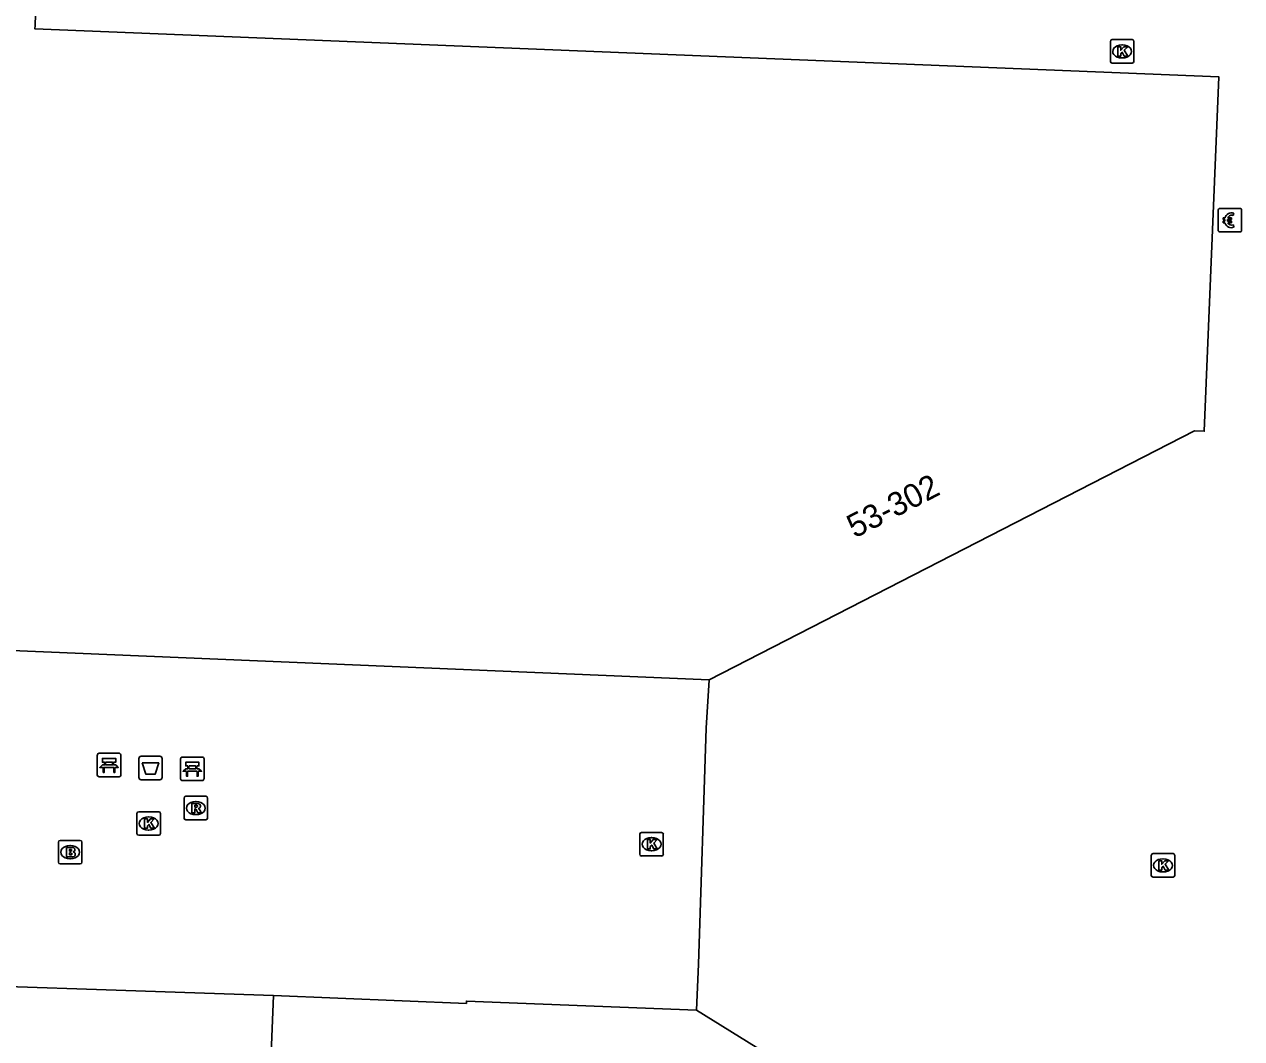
# Model space of a CAD drawing. Extents: x 160891 to 161384, y 386490 to 386907.
# Drawn here: x 161186.2 to 161238, y 386705.9 to 386749.1 of the extents above; entities that cross this region are included whole.
import ezdxf

# ---------------------------------------------------------------- set-up
doc = ezdxf.new("R2010")
doc.units = 0
for name, color, linetype in [('IMGEO_Afvalbak', 7, 'Continuous'), ('IMGEO_Bank', 7, 'Continuous'), ('IMGEO_Betaalautomaat', 7, 'Continuous'), ('IMGEO_Brandkraan', 7, 'Continuous'), ('IMGEO_Hek', 7, 'Continuous'), ('IMGEO_Kolk', 7, 'Continuous'), ('IMGEO_Pand', 7, 'Continuous'), ('IMGEO_Pand_nummerreeks', 7, 'Continuous'), ('IMGEO_Rioolput', 7, 'Continuous'), ('IMGEO_Voetgangersgebied_open', 7, 'Continuous')]:
    doc.layers.add(name, color=color, linetype=linetype)

msp = doc.modelspace()

# ---------------------------------------------------------------- linework, layer by layer
at = {"layer": 'IMGEO_Afvalbak'}
for p, q in [((161191.071, 386717.061), (161191.071, 386717.861)), ((161191.071, 386717.861), (161191.071, 386717.061)), ((161191.171, 386717.961), (161191.961, 386717.961)), ((161191.961, 386717.961), (161191.171, 386717.961)), ((161192.061, 386717.861), (161192.061, 386717.061)), ((161192.061, 386717.061), (161192.061, 386717.861)), ((161191.961, 386716.961), (161191.171, 386716.961)), ((161191.171, 386716.961), (161191.961, 386716.961))]:
    msp.add_line(p, q, dxfattribs=at)
msp.add_lwpolyline([(161191.214, 386717.675), (161191.918, 386717.675), (161191.769, 386717.205), (161191.363, 386717.205), (161191.214, 386717.675)], dxfattribs=at)
for centre, start, end in [((161191.171, 386717.861), 90, 180), ((161191.171, 386717.861), 90, 180), ((161191.961, 386717.861), 0, 90), ((161191.961, 386717.861), 360, 90), ((161191.171, 386717.061), 180, 270), ((161191.171, 386717.061), 180, 270), ((161191.961, 386717.061), 270, 0), ((161191.961, 386717.061), 270, 0)]:
    msp.add_arc(centre, 0.1, start, end, dxfattribs=at)
at = {"layer": 'IMGEO_Bank'}
for p, q in [((161189.304, 386717.165), (161189.304, 386718.006)), ((161189.304, 386718.006), (161189.304, 386717.165)), ((161189.379, 386718.09), (161190.22, 386718.09)), ((161190.22, 386718.09), (161189.379, 386718.09)), ((161189.613, 386717.596), (161189.613, 386717.702)), ((161189.657, 386717.702), (161189.657, 386717.596)), ((161189.945, 386717.708), (161189.663, 386717.708)), ((161189.951, 386717.596), (161189.951, 386717.702)), ((161189.995, 386717.702), (161189.995, 386717.596)), ((161190.304, 386718.015), (161190.304, 386717.174)), ((161190.304, 386717.174), (161190.304, 386718.015)), ((161192.844, 386717.003), (161192.844, 386717.844)), ((161192.844, 386717.844), (161192.844, 386717.003)), ((161192.919, 386717.928), (161193.76, 386717.928)), ((161193.76, 386717.928), (161192.919, 386717.928)), ((161193.844, 386717.853), (161193.844, 386717.012)), ((161193.844, 386717.012), (161193.844, 386717.853)), ((161190.001, 386717.488), (161189.608, 386717.488)), ((161189.663, 386717.59), (161189.945, 386717.59)), ((161193.541, 386717.326), (161193.148, 386717.326)), ((161193.153, 386717.434), (161193.153, 386717.54)), ((161193.197, 386717.54), (161193.197, 386717.434)), ((161193.485, 386717.546), (161193.203, 386717.546)), ((161193.203, 386717.428), (161193.485, 386717.428)), ((161193.491, 386717.434), (161193.491, 386717.54)), ((161193.535, 386717.54), (161193.535, 386717.434)), ((161190.229, 386717.09), (161189.388, 386717.09)), ((161189.388, 386717.09), (161190.229, 386717.09)), ((161193.769, 386716.928), (161192.928, 386716.928)), ((161192.928, 386716.928), (161193.769, 386716.928))]:
    msp.add_line(p, q, dxfattribs=at)
for points in [[(161189.607, 386717.708), (161189.521, 386717.708), (161189.521, 386717.869), (161190.084, 386717.869), (161190.084, 386717.708), (161190.001, 386717.708)], [(161193.147, 386717.546), (161193.061, 386717.546), (161193.061, 386717.707), (161193.624, 386717.707), (161193.624, 386717.546), (161193.541, 386717.546)], [(161189.551, 386717.488), (161189.409, 386717.488), (161189.521, 386717.59), (161189.607, 386717.59)], [(161189.601, 386717.481), (161189.601, 386717.274), (161189.558, 386717.274), (161189.558, 386717.481)], [(161190.001, 386717.59), (161190.084, 386717.59), (161190.196, 386717.488), (161190.057, 386717.488)], [(161190.051, 386717.481), (161190.051, 386717.274), (161190.007, 386717.274), (161190.007, 386717.481)], [(161193.091, 386717.326), (161192.949, 386717.326), (161193.061, 386717.428), (161193.147, 386717.428)], [(161193.141, 386717.319), (161193.141, 386717.112), (161193.098, 386717.112), (161193.098, 386717.319)], [(161193.541, 386717.428), (161193.624, 386717.428), (161193.736, 386717.326), (161193.597, 386717.326)], [(161193.591, 386717.319), (161193.591, 386717.112), (161193.547, 386717.112), (161193.547, 386717.319)]]:
    msp.add_lwpolyline(points, dxfattribs=at)
for centre, radius, start, end in [((161189.382, 386718.012), 0.0779, 92.4484, 184.2845), ((161189.382, 386718.012), 0.0779, 92.4484, 184.2845), ((161189.606, 386717.701), 0.00671, 2.8957, 87.1043), ((161189.663, 386717.701), 0.00671, 92.8957, 177.1043), ((161189.945, 386717.701), 0.00671, 2.8957, 87.1043), ((161190.002, 386717.701), 0.00671, 92.8957, 177.1043), ((161190.226, 386718.012), 0.0779, 2.4484, 94.2845), ((161190.226, 386718.012), 0.0779, 2.4484, 94.2845), ((161192.922, 386717.85), 0.0779, 92.4484, 184.2845), ((161192.922, 386717.85), 0.0779, 92.4484, 184.2845), ((161193.766, 386717.85), 0.0779, 2.4484, 94.2845), ((161193.766, 386717.85), 0.0779, 2.4484, 94.2845), ((161189.382, 386717.168), 0.0779, 182.4484, 274.2845), ((161189.382, 386717.168), 0.0779, 182.4484, 274.2845), ((161189.551, 386717.481), 0.00671, 2.8957, 87.1043), ((161189.608, 386717.481), 0.00671, 92.8957, 177.1043), ((161189.606, 386717.597), 0.00671, 272.8957, 357.1043), ((161189.663, 386717.597), 0.00671, 182.8957, 267.1043), ((161189.945, 386717.597), 0.00671, 272.8957, 357.1043), ((161190.002, 386717.597), 0.00671, 182.8957, 267.1043), ((161190, 386717.481), 0.00671, 2.8957, 87.1043), ((161190.057, 386717.481), 0.00671, 92.8957, 177.1043), ((161190.226, 386717.168), 0.0779, 272.4484, 4.2845), ((161190.226, 386717.168), 0.0779, 272.4484, 4.2845), ((161193.091, 386717.319), 0.00671, 2.8957, 87.1043), ((161193.148, 386717.319), 0.00671, 92.8957, 177.1043), ((161193.146, 386717.539), 0.00671, 2.8957, 87.1043), ((161193.146, 386717.435), 0.00671, 272.8957, 357.1043), ((161193.203, 386717.539), 0.00671, 92.8957, 177.1043), ((161193.203, 386717.435), 0.00671, 182.8957, 267.1043), ((161193.485, 386717.539), 0.00671, 2.8957, 87.1043), ((161193.485, 386717.435), 0.00671, 272.8957, 357.1043), ((161193.542, 386717.539), 0.00671, 92.8957, 177.1043), ((161193.542, 386717.435), 0.00671, 182.8957, 267.1043), ((161193.54, 386717.319), 0.00671, 2.8957, 87.1043), ((161193.597, 386717.319), 0.00671, 92.8957, 177.1043), ((161192.922, 386717.006), 0.0779, 182.4484, 274.2845), ((161192.922, 386717.006), 0.0779, 182.4484, 274.2845), ((161193.766, 386717.006), 0.0779, 272.4484, 4.2845), ((161193.766, 386717.006), 0.0779, 272.4484, 4.2845)]:
    msp.add_arc(centre, radius, start, end, dxfattribs=at)
at = {"layer": 'IMGEO_Betaalautomaat'}
for p, q in [((161236.966, 386740.342), (161236.966, 386741.183)), ((161236.966, 386741.183), (161236.966, 386740.342)), ((161237.041, 386741.266), (161237.882, 386741.266)), ((161237.882, 386741.266), (161237.041, 386741.266)), ((161237.628, 386741.071), (161237.611, 386740.971)), ((161237.965, 386741.192), (161237.965, 386740.351)), ((161237.965, 386740.351), (161237.965, 386741.192)), ((161237.249, 386740.73), (161237.249, 386740.798)), ((161237.37, 386740.798), (161237.37, 386740.73)), ((161237.615, 386740.565), (161237.637, 386740.478)), ((161237.891, 386740.267), (161237.05, 386740.267)), ((161237.05, 386740.267), (161237.891, 386740.267))]:
    msp.add_line(p, q, dxfattribs=at)
for points in [[(161237.249, 386740.798), (161237.18, 386740.798), (161237.18, 386740.867), (161237.259, 386740.867)], [(161237.254, 386740.661), (161237.18, 386740.661), (161237.18, 386740.73), (161237.249, 386740.73)], [(161237.381, 386740.867), (161237.528, 386740.867), (161237.528, 386740.798), (161237.37, 386740.798)], [(161237.37, 386740.73), (161237.528, 386740.73), (161237.528, 386740.661), (161237.384, 386740.661)]]:
    msp.add_lwpolyline(points, dxfattribs=at)
for centre, radius, start, end in [((161237.044, 386741.189), 0.0779, 92.4484, 184.2845), ((161237.044, 386741.189), 0.0779, 92.4484, 184.2845), ((161237.542, 386740.791), 0.293, 73.014, 165.0139), ((161237.548, 386740.804), 0.179, 69.3236, 159.5683), ((161237.888, 386741.189), 0.0779, 2.4484, 94.2845), ((161237.888, 386741.189), 0.0779, 2.4484, 94.2845), ((161237.515, 386740.716), 0.267, 191.8096, 297.0389), ((161237.548, 386740.731), 0.179, 202.7625, 291.8693), ((161237.044, 386740.345), 0.0779, 182.4484, 274.2845), ((161237.044, 386740.345), 0.0779, 182.4484, 274.2845), ((161237.888, 386740.345), 0.0779, 272.4484, 4.2845), ((161237.888, 386740.345), 0.0779, 272.4484, 4.2845)]:
    msp.add_arc(centre, radius, start, end, dxfattribs=at)
at = {"layer": 'IMGEO_Brandkraan'}
for p, q in [((161187.649, 386713.454), (161187.649, 386714.306)), ((161187.724, 386714.38), (161188.576, 386714.38)), ((161188.137, 386714.16), (161188.162, 386714.16)), ((161188.65, 386714.306), (161188.65, 386713.454)), ((161188.16, 386713.6), (161188.135, 386713.6)), ((161188.576, 386713.38), (161187.724, 386713.38))]:
    msp.add_line(p, q, dxfattribs=at)
for points in [[(161187.649, 386713.454), (161187.649, 386714.306)], [(161187.724, 386714.38), (161188.576, 386714.38)], [(161187.997, 386714.08), (161187.997, 386713.68), (161188.21, 386713.68)], [(161188.228, 386714.08), (161187.997, 386714.08)], [(161188.65, 386714.306), (161188.65, 386713.454)], [(161188.176, 386713.999), (161188.122, 386713.999), (161188.122, 386713.923)], [(161188.122, 386713.923), (161188.175, 386713.923)], [(161188.184, 386713.847), (161188.122, 386713.847), (161188.122, 386713.766)], [(161188.122, 386713.766), (161188.184, 386713.766)], [(161188.576, 386713.38), (161187.724, 386713.38)]]:
    msp.add_lwpolyline(points, dxfattribs=at)
for centre, radius, start, end in [((161187.726, 386714.304), 0.0765, 91.552, 178.448), ((161187.726, 386714.304), 0.0765, 91.552, 178.448), ((161188.232, 386713.935), 0.145, 59.4692, 91.5367), ((161188.257, 386713.982), 0.0922, 285.5137, 58.1501), ((161188.574, 386714.304), 0.0765, 1.552, 88.448), ((161188.574, 386714.304), 0.0765, 1.552, 88.448), ((161188.177, 386713.961), 0.0379, 267.8285, 90.9355), ((161188.185, 386713.806), 0.0404, 269.8759, 90.5077), ((161188.216, 386713.931), 0.251, 268.6676, 293.5347), ((161188.262, 386713.79), 0.105, 301.3115, 78.989), ((161187.726, 386713.456), 0.0765, 181.552, 268.448), ((161187.726, 386713.456), 0.0765, 181.552, 268.448), ((161188.574, 386713.456), 0.0765, 271.552, 358.448), ((161188.574, 386713.456), 0.0765, 271.552, 358.448)]:
    msp.add_arc(centre, radius, start, end, dxfattribs=at)
for centre, major_axis, ratio, start_param, end_param in [((161188.136, 386713.88), (-0.387, 0.002), 0.722429, 4.712389, 7.853982), ((161188.161, 386713.88), (-0.39, 0.002), 0.717154, 1.570796, 4.712389)]:
    msp.add_ellipse(centre, major_axis=major_axis, ratio=ratio, start_param=start_param, end_param=end_param, dxfattribs=at)
at = {"layer": 'IMGEO_Hek'}
for points in [[(161215.329, 386721.218), (161215.194, 386719.154)], [(161215.194, 386719.154), (161214.868, 386709.114)], [(161214.868, 386709.114), (161214.777, 386707.152)]]:
    msp.add_lwpolyline(points, dxfattribs=at)
at = {"layer": 'IMGEO_Kolk'}
for p, q in [((161232.382, 386747.523), (161232.382, 386748.375)), ((161232.457, 386748.449), (161233.309, 386748.449)), ((161232.87, 386748.229), (161232.895, 386748.229)), ((161233.383, 386748.375), (161233.383, 386747.523)), ((161233.309, 386747.449), (161232.457, 386747.449)), ((161232.893, 386747.669), (161232.868, 386747.669)), ((161191.062, 386715.599), (161191.914, 386715.599)), ((161190.987, 386714.673), (161190.987, 386715.525)), ((161191.475, 386715.379), (161191.5, 386715.379)), ((161191.988, 386715.525), (161191.988, 386714.673)), ((161191.914, 386714.599), (161191.062, 386714.599)), ((161191.498, 386714.819), (161191.473, 386714.819)), ((161212.372, 386713.791), (161212.372, 386714.643)), ((161212.447, 386714.717), (161213.299, 386714.717)), ((161213.373, 386714.643), (161213.373, 386713.791)), ((161212.86, 386714.497), (161212.885, 386714.497)), ((161213.299, 386713.717), (161212.447, 386713.717)), ((161212.883, 386713.937), (161212.858, 386713.937)), ((161234.121, 386712.892), (161234.121, 386713.744)), ((161234.196, 386713.818), (161235.048, 386713.818)), ((161234.609, 386713.598), (161234.634, 386713.598)), ((161235.122, 386713.744), (161235.122, 386712.892)), ((161234.632, 386713.038), (161234.607, 386713.038)), ((161235.048, 386712.818), (161234.196, 386712.818))]:
    msp.add_line(p, q, dxfattribs=at)
for points in [[(161232.382, 386747.523), (161232.382, 386748.375)], [(161232.457, 386748.449), (161233.309, 386748.449)], [(161233.383, 386748.375), (161233.383, 386747.523)], [(161232.703, 386748.149), (161232.826, 386748.149), (161232.826, 386747.998), (161232.956, 386748.149), (161233.12, 386748.149), (161232.974, 386747.998), (161233.127, 386747.749), (161232.975, 386747.749), (161232.89, 386747.913), (161232.826, 386747.846), (161232.826, 386747.749), (161232.703, 386747.749), (161232.703, 386748.149)], [(161233.309, 386747.449), (161232.457, 386747.449)], [(161191.062, 386715.599), (161191.914, 386715.599)], [(161190.987, 386714.673), (161190.987, 386715.525)], [(161191.308, 386715.299), (161191.431, 386715.299), (161191.431, 386715.148), (161191.561, 386715.299), (161191.725, 386715.299), (161191.579, 386715.148), (161191.732, 386714.899), (161191.58, 386714.899), (161191.495, 386715.063), (161191.431, 386714.996), (161191.431, 386714.899), (161191.308, 386714.899), (161191.308, 386715.299)], [(161191.988, 386715.525), (161191.988, 386714.673)], [(161191.914, 386714.599), (161191.062, 386714.599)], [(161212.372, 386713.791), (161212.372, 386714.643)], [(161212.447, 386714.717), (161213.299, 386714.717)], [(161213.373, 386714.643), (161213.373, 386713.791)], [(161212.693, 386714.417), (161212.816, 386714.417), (161212.816, 386714.266), (161212.946, 386714.417), (161213.11, 386714.417), (161212.964, 386714.266), (161213.117, 386714.017), (161212.965, 386714.017), (161212.88, 386714.181), (161212.816, 386714.114), (161212.816, 386714.017), (161212.693, 386714.017), (161212.693, 386714.417)], [(161213.299, 386713.717), (161212.447, 386713.717)], [(161234.121, 386712.892), (161234.121, 386713.744)], [(161234.196, 386713.818), (161235.048, 386713.818)], [(161234.442, 386713.518), (161234.565, 386713.518), (161234.565, 386713.367), (161234.695, 386713.518), (161234.859, 386713.518), (161234.713, 386713.367), (161234.866, 386713.118), (161234.714, 386713.118), (161234.629, 386713.282), (161234.565, 386713.215), (161234.565, 386713.118), (161234.442, 386713.118), (161234.442, 386713.518)], [(161235.122, 386713.744), (161235.122, 386712.892)], [(161235.048, 386712.818), (161234.196, 386712.818)]]:
    msp.add_lwpolyline(points, dxfattribs=at)
for centre, start, end in [((161232.459, 386748.373), 91.552, 178.448), ((161232.459, 386748.373), 91.552, 178.448), ((161233.307, 386748.373), 1.552, 88.448), ((161233.307, 386748.373), 1.552, 88.448), ((161232.459, 386747.525), 181.552, 268.448), ((161232.459, 386747.525), 181.552, 268.448), ((161233.307, 386747.525), 271.552, 358.448), ((161233.307, 386747.525), 271.552, 358.448), ((161191.064, 386715.523), 91.552, 178.448), ((161191.064, 386715.523), 91.552, 178.448), ((161191.912, 386715.523), 1.552, 88.448), ((161191.912, 386715.523), 1.552, 88.448), ((161191.064, 386714.675), 181.552, 268.448), ((161191.064, 386714.675), 181.552, 268.448), ((161191.912, 386714.675), 271.552, 358.448), ((161191.912, 386714.675), 271.552, 358.448), ((161212.449, 386714.641), 91.552, 178.448), ((161212.449, 386714.641), 91.552, 178.448), ((161213.297, 386714.641), 1.552, 88.448), ((161213.297, 386714.641), 1.552, 88.448), ((161212.449, 386713.793), 181.552, 268.448), ((161212.449, 386713.793), 181.552, 268.448), ((161213.297, 386713.793), 271.552, 358.448), ((161213.297, 386713.793), 271.552, 358.448), ((161234.198, 386713.742), 91.552, 178.448), ((161234.198, 386713.742), 91.552, 178.448), ((161235.046, 386713.742), 1.552, 88.448), ((161235.046, 386713.742), 1.552, 88.448), ((161234.198, 386712.894), 181.552, 268.448), ((161234.198, 386712.894), 181.552, 268.448), ((161235.046, 386712.894), 271.552, 358.448), ((161235.046, 386712.894), 271.552, 358.448)]:
    msp.add_arc(centre, 0.0765, start, end, dxfattribs=at)
for centre, major_axis, ratio, start_param, end_param in [((161232.869, 386747.949), (-0.387, 0.002), 0.722429, 4.712389, 7.853982), ((161232.894, 386747.949), (-0.39, 0.002), 0.717154, 1.570796, 4.712389), ((161191.474, 386715.099), (-0.387, 0.002), 0.722429, 4.712389, 7.853982), ((161191.499, 386715.099), (-0.39, 0.002), 0.717154, 1.570796, 4.712389), ((161212.859, 386714.217), (-0.387, 0.002), 0.722429, 4.712389, 7.853982), ((161212.884, 386714.217), (-0.39, 0.002), 0.717154, 1.570796, 4.712389), ((161234.608, 386713.318), (-0.387, 0.002), 0.722429, 4.712389, 7.853982), ((161234.633, 386713.318), (-0.39, 0.002), 0.717154, 1.570796, 4.712389)]:
    msp.add_ellipse(centre, major_axis=major_axis, ratio=ratio, start_param=start_param, end_param=end_param, dxfattribs=at)
at = {"layer": 'IMGEO_Pand'}
for points in [[(161215.329, 386721.218), (161235.961, 386731.803), (161236.376, 386731.786), (161236.989, 386746.871), (161186.65, 386748.905), (161186.656, 386749.048), (161186.694, 386750), (161186.852, 386753.913), (161187.146, 386761.187)], [(161173.519, 386722.968), (161215.329, 386721.218)], [(161216.005, 386647.458), (161194.302, 386648.347), (161194.32, 386648.757), (161194.42, 386648.752), (161196.801, 386707.775)], [(161196.801, 386707.775), (161204.996, 386707.443), (161205, 386707.543), (161214.777, 386707.152)], [(161214.777, 386707.152), (161234.482, 386694.929), (161234.896, 386694.91), (161234.274, 386679.434), (161217.32, 386680.124), (161216.005, 386647.458)]]:
    msp.add_lwpolyline(points, dxfattribs=at)
at = {"layer": 'IMGEO_Rioolput'}
for p, q in [((161192.992, 386715.33), (161192.992, 386716.182)), ((161193.067, 386716.256), (161193.919, 386716.256)), ((161193.993, 386716.182), (161193.993, 386715.33)), ((161193.48, 386716.036), (161193.505, 386716.036)), ((161193.919, 386715.256), (161193.067, 386715.256)), ((161193.503, 386715.476), (161193.478, 386715.476))]:
    msp.add_line(p, q, dxfattribs=at)
for points in [[(161192.992, 386715.33), (161192.992, 386716.182)], [(161193.067, 386716.256), (161193.919, 386716.256)], [(161193.993, 386716.182), (161193.993, 386715.33)], [(161193.581, 386715.954), (161193.329, 386715.956), (161193.329, 386715.556)], [(161193.329, 386715.556), (161193.453, 386715.556), (161193.453, 386715.718), (161193.464, 386715.718)], [(161193.507, 386715.875), (161193.453, 386715.875), (161193.453, 386715.794)], [(161193.453, 386715.794), (161193.505, 386715.794)], [(161193.511, 386715.689), (161193.582, 386715.556), (161193.722, 386715.556), (161193.657, 386715.682)], [(161193.919, 386715.256), (161193.067, 386715.256)]]:
    msp.add_lwpolyline(points, dxfattribs=at)
for centre, radius, start, end in [((161193.069, 386716.18), 0.0765, 91.552, 178.448), ((161193.069, 386716.18), 0.0765, 91.552, 178.448), ((161193.917, 386716.18), 0.0765, 1.552, 88.448), ((161193.917, 386716.18), 0.0765, 1.552, 88.448), ((161193.463, 386715.665), 0.0533, 26.0293, 88.6989), ((161193.489, 386715.983), 0.19, 274.7715, 282.9687), ((161193.513, 386715.779), 0.0964, 77.0061, 93.1865), ((161193.527, 386715.836), 0.0378, 276.6634, 79.6772), ((161193.58, 386715.844), 0.109, 350.3612, 89.416), ((161193.578, 386715.844), 0.112, 277.5842, 350.9817), ((161193.562, 386715.629), 0.108, 29.5134, 73.7905), ((161193.069, 386715.332), 0.0765, 181.552, 268.448), ((161193.069, 386715.332), 0.0765, 181.552, 268.448), ((161193.917, 386715.332), 0.0765, 271.552, 358.448), ((161193.917, 386715.332), 0.0765, 271.552, 358.448)]:
    msp.add_arc(centre, radius, start, end, dxfattribs=at)
for centre, major_axis, ratio, start_param, end_param in [((161193.479, 386715.756), (-0.387, 0.002), 0.722429, 4.712389, 7.853982), ((161193.504, 386715.756), (-0.39, 0.002), 0.717154, 1.570796, 4.712389)]:
    msp.add_ellipse(centre, major_axis=major_axis, ratio=ratio, start_param=start_param, end_param=end_param, dxfattribs=at)
at = {"layer": 'IMGEO_Voetgangersgebied_open'}
for points in [[(161215.329, 386721.218), (161215.194, 386719.154), (161214.868, 386709.114), (161214.777, 386707.152)], [(161196.801, 386707.775), (161178.374, 386708.407)]]:
    msp.add_lwpolyline(points, dxfattribs=at)

# ---------------------------------------------------------------- texts
at = {"layer": 'IMGEO_Pand_nummerreeks'}
msp.add_text('53-302', height=1, rotation=27.1582, dxfattribs=at).set_placement((161221.509, 386727.221))

doc.saveas('drawing.dxf')
